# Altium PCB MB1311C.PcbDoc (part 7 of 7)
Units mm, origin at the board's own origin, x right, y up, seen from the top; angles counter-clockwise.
Board outline 100.03 x 67.03 mm, 6 copper layers (Top Layer, layer2, layer3, layer4, layer5, Bottom Layer), stack 1.208 mm thick; 366 components, 356 nets, 1582 pads, 964 vias.
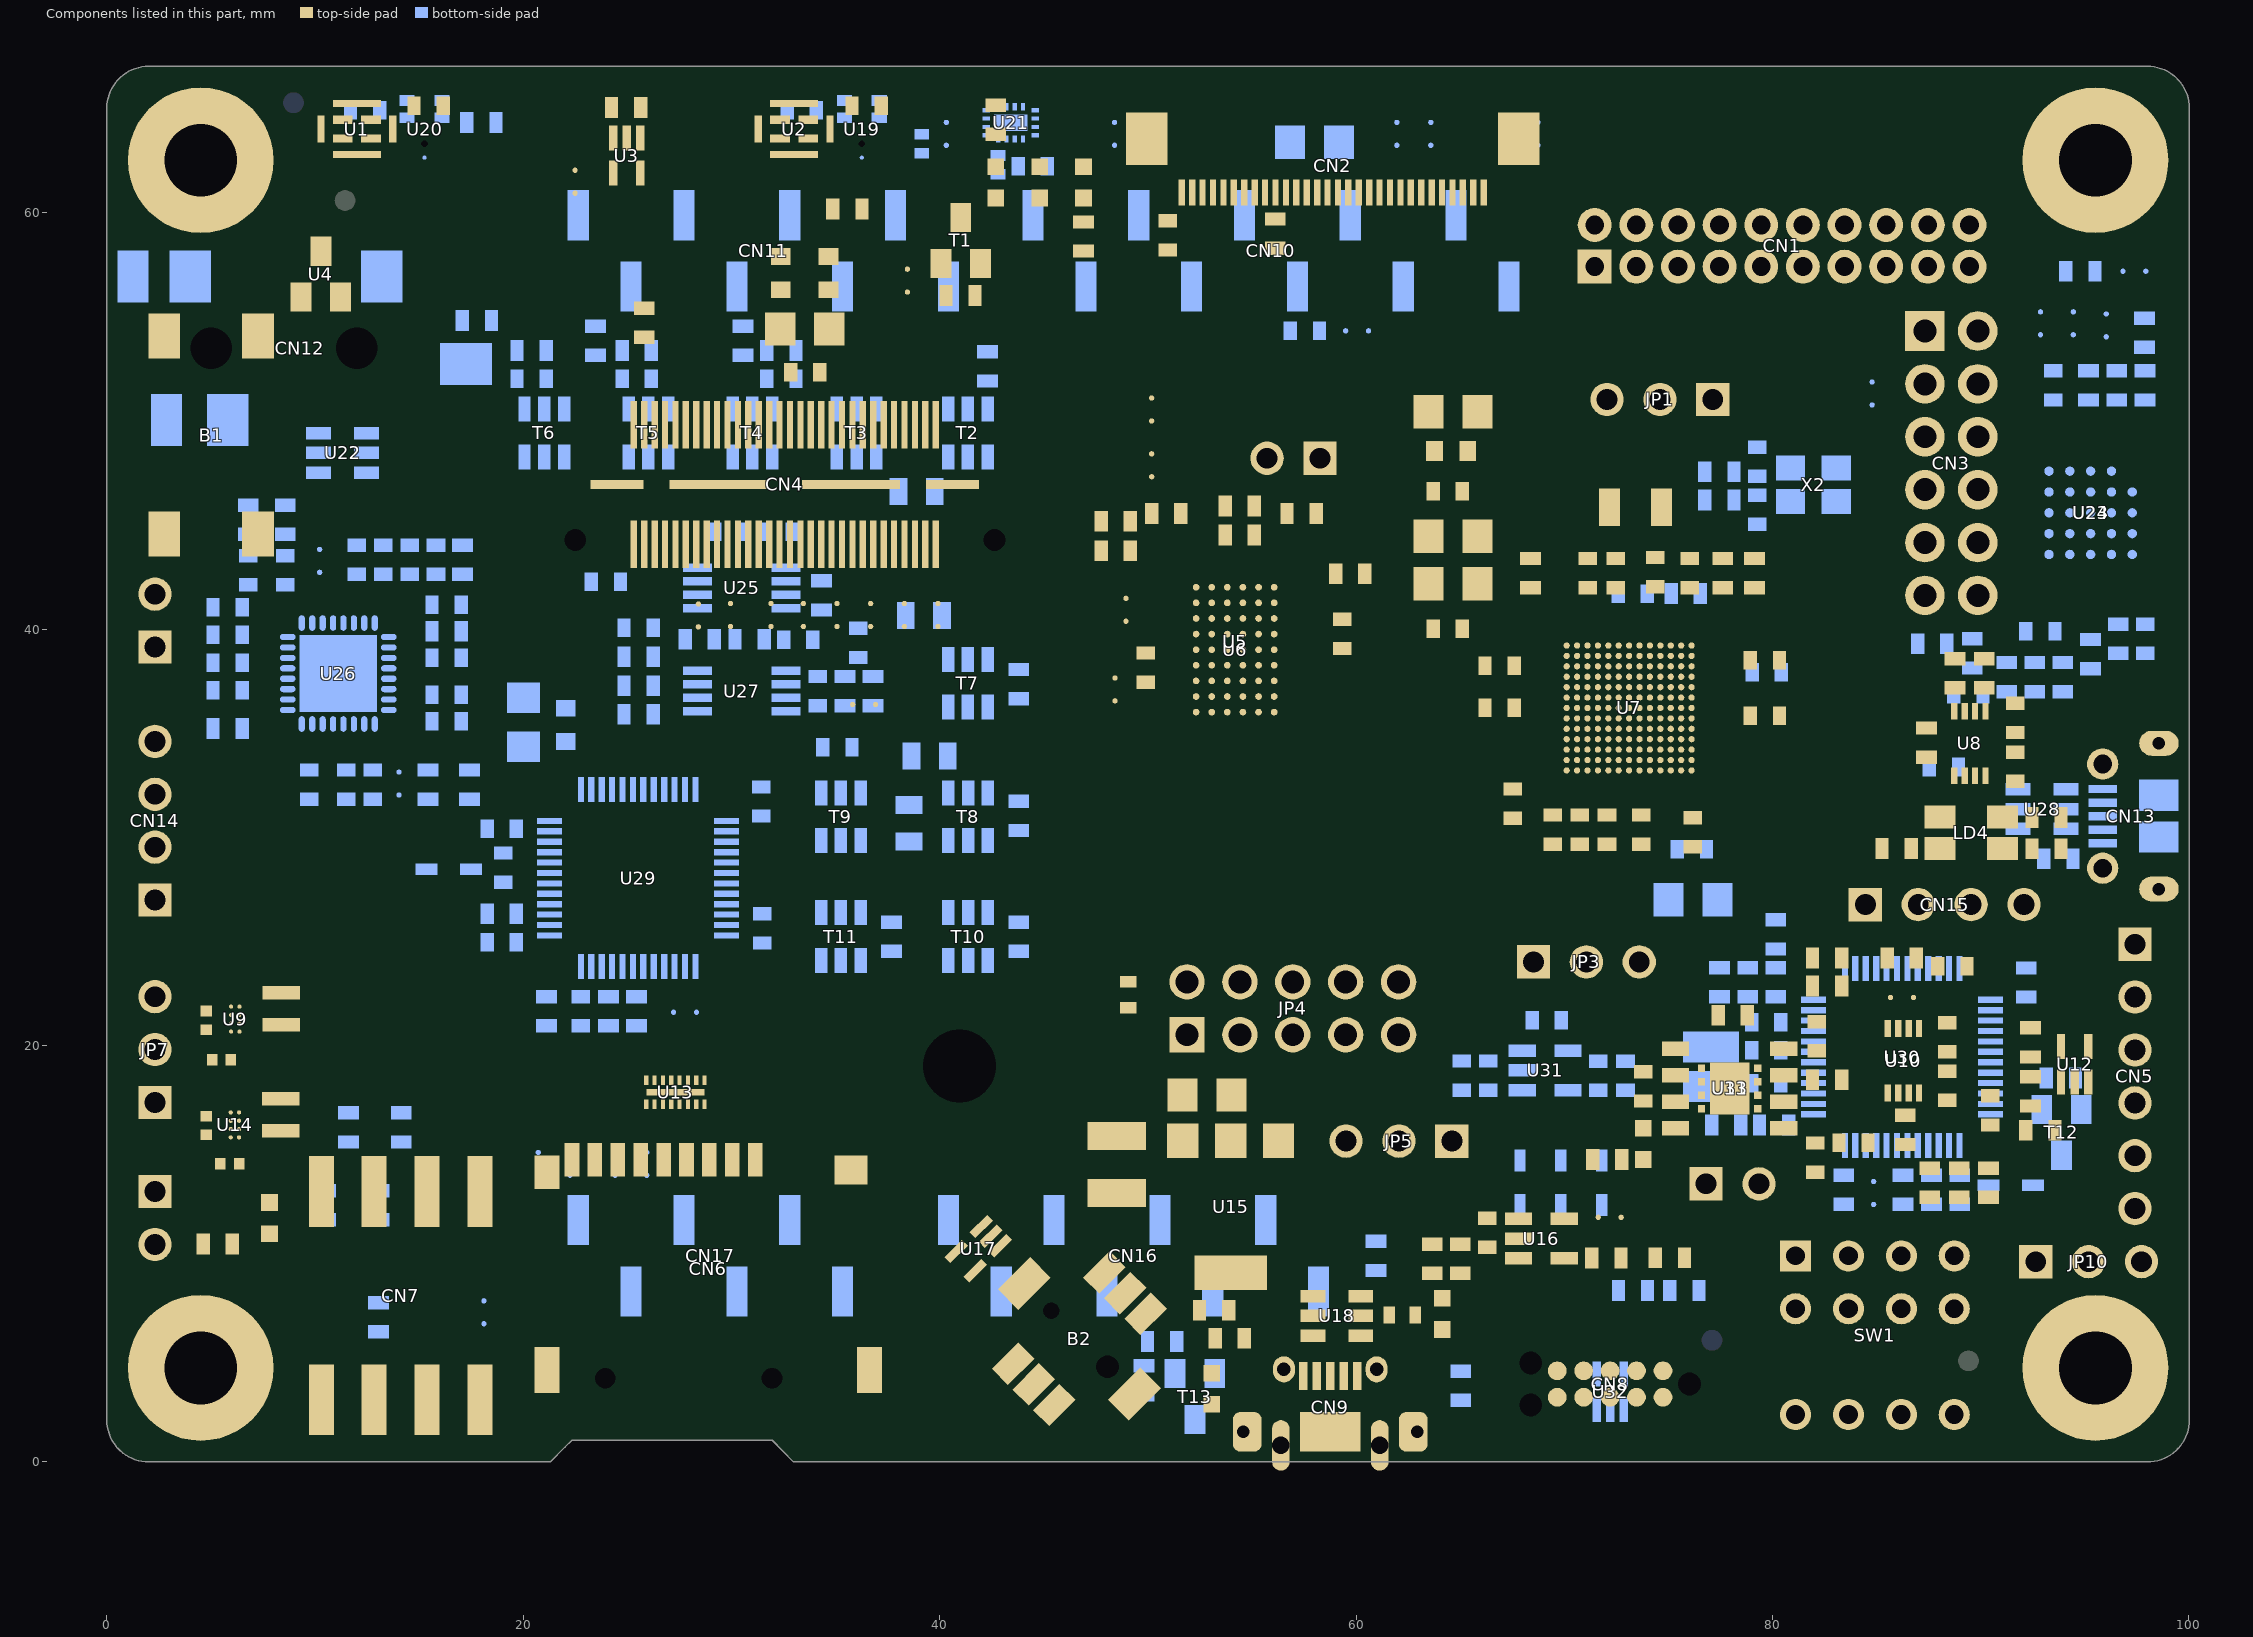
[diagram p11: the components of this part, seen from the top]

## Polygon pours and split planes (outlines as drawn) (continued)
+5V on layer4 "+5V_L04_P742" (solid, remove dead copper, pour order 742): 34.213,21.013 34.213,21.913 36.913,24.613 37.213,24.613 43.413,24.613 44.913,26.113 63.013,26.113 63.713,25.413 63.713,24.113 63.713,22.713 62.663,21.663 50.813,21.663 48.963,19.813 35.413,19.813
T50_4 on layer4 "T50_4_L04_P736" (solid, remove dead copper, pour order 736): 68.863,54.413 68.863,55.513 68.063,56.313 38.713,56.313 38.313,55.913 38.313,47.613 38.813,47.113 39.413,47.113 39.813,47.513 39.913,47.613 39.913,49.413 44.513,54.013 44.913,54.413 46.413,54.413
+3V3 on layer4 "+3V3_L04_P732" (solid, remove dead copper, pour order 732): 36.441,56.309 36.013,55.881 36.013,51.563 32.213,47.763 32.213,47.613 32.213,46.963 36.163,43.013 37.413,43.013 46.813,43.013 48.813,45.013 49.913,46.113 49.913,47.413 49.913,47.713 49.413,48.213 44.013,48.213 41.313,45.513 40.063,45.513 38.113,47.463 38.113,55.963 37.767,56.309
+3V3_ST_LINK on layer4 "+3V3_ST_LINK_L04_P716" (solid, remove dead copper, pour order 716): 80.813,24.513 85.313,29.013 89.213,29.013 90.213,28.013 90.213,26.013 90.213,25.913 89.313,25.013 89.313,20.413 89.313,19.663 87.413,17.763 87.413,16.813 87.413,16.513 87.813,16.113 87.913,16.013 88.513,16.013 88.613,16.013 89.413,16.813 92.013,16.813 94.113,14.713 94.213,14.613 94.213,13.113 94.213,12.713 92.413,10.913 92.363,10.863 79.913,10.863 79.013,11.763 79.013,13.473 80.813,15.273
1V8_CODEC on layer4 "1V8_CODEC_L04_P710" (solid, remove dead copper, pour order 710): 5.613,39.413 9.213,43.013 12.713,43.013 13.513,42.213 13.513,34.963 10.763,32.213 6.013,32.213 5.613,32.613
U5V_ST_LINK on layer4 "U5V_ST_LINK_L04_P746" (solid, remove dead copper, pour order 746): 51.963,21.063 65.963,21.063 71.013,16.013 71.013,15.113 70.363,14.463 68.913,14.463 67.613,14.463 65.313,16.763 64.363,17.713 54.113,17.713 52.363,17.713 51.213,18.863 51.213,20.313
VDD_STL on layer4 "VDD_STL_L04_P714" (solid, remove dead copper, pour order 714): 87.263,29.413 87.263,33.863 89.213,35.813 95.613,35.813 96.613,34.813 96.613,11.113 96.613,9.813 96.013,9.213 94.613,9.213 94.513,9.213 94.113,9.613 93.913,9.813 93.913,11.963 94.513,12.563 94.513,14.813 92.213,17.113 89.413,17.113 89.013,16.713 88.613,16.313 88.213,16.313 88.113,16.313 87.913,16.513 87.713,16.713 87.713,17.613 87.713,17.713 89.213,19.213 89.563,19.563 89.563,24.763 90.613,25.813 90.613,26.513 90.613,28.113 89.913,28.813 89.313,29.413
+1V8 on layer4 "+1V8_L04_P722" (solid, remove dead copper, pour order 722): 1.113,21.713 0.613,22.213 0.613,49.213 2.163,50.763 21.113,50.763 22.263,49.613 22.263,48.863 21.263,47.863 17.313,47.863 12.763,43.313 9.113,43.313 5.413,39.613 5.413,31.713 4.813,31.113 4.813,22.013 4.513,21.713
GND on layer5 "GND_L05_P705" (solid, remove dead copper, pour order 705): 0.013,67.013 0.1,66.926 100.068,66.926 100.068,0.068 100.013,0.013 0.013,0.013
AGND on layer5 "AGND_L05_P581" (solid, remove dead copper, pour order 581): 7.977,32.913 17.813,32.913 18.913,34.013 18.913,43.513 18.913,52.713 17.313,54.313 13.313,58.313 8.313,58.313 3.24,58.313 2.013,57.086 2.013,44.813 2.313,44.513 3.988,42.838 3.988,36.903
T50_6 on Bottom Layer "T50_6_L06_P706" (solid, remove dead copper, pour order 706): 36.213,47.413 37.313,46.313 37.313,45.513 38.613,45.513 38.613,41.527 37.793,41.527 37.793,39.777 39.65,39.777 39.65,34.768 38.073,34.768 38.073,33.018 39.208,33.018 39.213,32.413 37.613,32.413 36.913,33.113 36.913,34.913 36.913,35.313 37.713,36.113 37.713,38.013 36.718,39.008 36.718,41.708 35.613,42.813 33.468,42.813 32.713,42.813 32.713,43.113 33.113,43.113 33.513,43.513 33.913,43.913 33.913,46.213 33.913,46.313 34.813,47.213 34.813,47.413
NetCN5_1 on Bottom Layer "NETCN5_1_L06_P772" (solid, remove dead copper, pour order 772): 95.413,27.113 96.363,28.063 97.013,28.063 98.513,28.063 99.413,27.163 99.413,9.813 98.663,9.063 98.513,8.913 98.213,8.913 97.113,8.913 97.013,9.013 95.713,10.313 95.713,10.963 95.713,19.013 95.413,19.313
VIN on Bottom Layer "VIN_L06_P764" (solid, remove dead copper, pour order 764): 40.213,12.063 43.613,12.063 47.813,16.263 47.813,16.463 47.813,17.363 48.263,17.813 48.313,17.863 49.163,17.863 49.413,17.863 50.113,17.163 50.163,17.113 50.163,14.813 50.163,14.563 47.263,11.663 47.263,10.463 47.263,9.913 46.963,9.613 46.213,8.863 41.363,8.863 40.963,8.863 40.213,9.613
SH2_D on Bottom Layer "SH2_D_L06_P708" (solid, remove dead copper, pour order 708): 37.913,29.013 41.113,29.013 41.613,28.513 41.613,27.226 39.926,27.226 39.913,27.213 39.848,27.148 39.848,25.913 38.713,25.913 38.613,26.013 38.613,26.613 38.613,26.813 37.913,27.513
ARD_5V on Bottom Layer "ARD_5V_L06_P762" (solid, remove dead copper, pour order 762): 62.863,15.213 62.863,16.063 62.313,16.613 61.513,17.413 59.463,17.413 53.513,17.413 49.463,13.363 47.763,11.663 47.763,7.463 49.013,7.463 49.063,7.513 49.463,7.513 52.063,10.113 55.113,13.163 55.163,13.163 57.763,13.163 58.063,13.463 58.363,13.763 61.863,13.763 62.263,13.763 62.863,14.363
+3V3_ST_LINK on Bottom Layer "+3V3_ST_LINK_L06_P770" (solid, remove dead copper, pour order 770): 71.213,18.113 73.313,18.113 73.513,17.913 73.563,17.863 73.563,17.063 73.563,15.813 76.463,12.913 76.613,12.763 79.763,12.763 79.863,12.763 80.213,12.413 80.213,11.813 80.113,11.713 79.963,11.563 76.263,11.563 75.363,11.563 74.763,12.163 72.363,14.563 72.363,15.213 71.213,16.363
5V_USB_CHARGER on Bottom Layer "5V_USB_CHARGER_L06_P768" (solid, remove dead copper, pour order 768): 81.813,14.063 81.813,11.413 80.563,10.163 80.187,9.787 73.457,9.787 71.739,9.787 71.063,10.463 70.963,10.563 70.963,11.863 70.963,12.463 70.463,12.963 70.463,13.413 70.713,13.663 72.263,13.663 74.563,11.363 77.713,11.363 80.013,11.363 80.413,11.763 80.413,13.763 80.413,14.063 80.563,14.213 80.663,14.313 81.563,14.313
5V_STL on Bottom Layer "5V_STL_L06_P774" (solid, remove dead copper, pour order 774): 85.613,10.163 87.263,11.813 87.513,11.813 89.498,11.813 90.213,12.528 90.213,13.613 88.663,13.613 88.613,13.663 88.613,13.913 89.463,14.763 91.833,14.763 92.963,13.633 92.963,12.588 91.238,10.863 88.213,10.863 86.763,9.413 85.813,9.413 85.613,9.613 85.613,9.713
+3V3 on Top Layer "+3V3_L01_P740" (solid, remove dead copper, pour order 740): 79.113,66.413 40.463,66.413 37.313,63.263 37.313,60.413 35.913,59.013 35.913,56.113 35.913,55.713 36.213,55.413 37.613,55.413 37.613,57.913 37.913,58.213 38.613,58.913 40.313,58.913 40.313,61.113 40.813,61.613 41.563,62.363 41.563,63.613 79.113,63.613
+5V on Top Layer "+5V_L01_P748" (solid, remove dead copper, pour order 748): 10.661,20.784 12.64,22.763 35.298,22.763 35.571,22.49 35.571,22.103 35.034,21.566 34.84,21.372 34.419,21.372 33.975,20.928 32.111,19.064 6.947,19.064 6.821,19.19 6.821,19.47 7.001,19.651 8.133,19.651 9.202,19.651 10.339,20.789
5V_USB_CHARGER on Top Layer "5V_USB_CHARGER_L01_P744" (solid, remove dead copper, pour order 744): 61.013,21.913 62.613,21.913 63.313,21.213 63.413,21.113 63.413,18.013 63.413,14.413 63.113,14.113 61.913,14.113 60.553,12.753 59.543,12.753 59.323,12.973 59.323,13.723 60.613,15.013 60.613,21.513
+3V3 on Top Layer "+3V3_L01_P704" (solid, remove dead copper, pour order 704): 10.013,18.113 9.413,18.713 2.213,18.713 1.713,18.213 1.713,17.213 2.613,16.313 4.373,16.313 4.373,16.593 4.373,16.953 4.733,16.953 5.303,17.523 7.103,17.523 7.503,17.123 10.013,17.123
+1V8 on Top Layer "+1V8_L01_P702" (solid, remove dead copper, pour order 702): 9.913,23.213 9.313,23.813 1.813,23.813 1.513,23.513 1.513,22.313 2.413,21.413 4.383,21.413 4.383,21.683 4.383,22.003 4.703,22.003 5.313,22.613 7.113,22.613 7.513,22.213 9.913,22.213
+5V on Top Layer "+5V_L01_P754" (solid, remove dead copper, pour order 754): 63.813,15.263 63.863,15.313 63.863,21.213 63.863,21.563 63.113,22.313 63.113,23.863 65.363,23.863 65.663,23.563 66.313,22.913 66.313,17.863 66.313,15.763 65.813,15.263
VDD1 on Top Layer "VDD1_L01_P756" (solid, remove dead copper, pour order 756): 16.573,28.363 21.002,23.934 21.002,23.594 20.671,23.263 18.113,23.263 11.313,23.263 10.963,23.613 9.113,25.463 9.113,25.513 1.813,25.513 1.563,25.763 1.513,25.813 1.513,27.863 1.513,27.913 1.963,28.363
+5V on Top Layer "+5V_L01_P750" (solid, remove dead copper, pour order 750): 72.813,12.463 73.713,12.463 73.763,12.413 73.763,11.163 75.913,11.163 76.363,10.713 76.363,8.763 76.363,7.813 78.813,5.363 80.213,3.963 82.863,3.963 84.113,3.963 84.963,3.113 84.963,2.063 84.963,1.663 85.313,1.313 87.113,1.313 87.163,1.313 87.463,1.613 87.413,1.663 87.413,4.013 85.363,6.063 82.363,6.063 80.913,6.063 80.413,6.563 77.963,9.013 77.963,11.563 77.413,12.113 77.313,12.213 75.063,12.213 74.813,12.463 74.063,13.213 73.263,13.213 72.913,13.213 72.813,13.113
GND on Top Layer "GND_L01_P780" (solid, remove dead copper, pour order 780): 81.125,19.525 78.725,19.525 78.525,19.325 78.525,16.525 79.625,15.425 80.425,14.625 80.425,12.95 79.8,12.325 78.75,12.325 78.075,13 78.075,14.275 77.675,14.675 77,14.675 76.675,15 76.675,15.575 77.275,16.175 77.275,19.55 77.825,20.1 81.125,20.1
+5V on layer3 "+5V_L03_P738" (solid, remove dead copper, pour order 738): 4.113,22.413 5.013,23.313 5.813,23.313 7.513,23.313 8.013,22.813 8.813,22.013 8.813,16.313 8.813,13.913 6.813,11.913 6.513,11.613 2.713,11.613 1.213,11.613 0.913,11.913 0.913,13.813 0.913,14.613 1.213,14.913 1.613,15.313 3.013,15.313 3.313,15.313 4.113,16.113
5V_USB_CHARGER on layer3 "5V_USB_CHARGER_L03_P718" (solid, remove dead copper, pour order 718): 83.413,12.813 84.413,13.813 84.413,20.338 95.713,31.638 95.713,33.113 95.113,33.713 93.813,33.713 89.213,33.713 89.113,33.713 84.413,29.013 82.813,27.413 82.813,23.513 80.763,21.463 80.763,12.813
5V_USB_CHARGER on layer3 "5V_USB_CHARGER_L03_P766" (solid, remove dead copper, pour order 766): 59.513,13.663 70.963,13.663 72.013,12.613 72.913,11.713 72.913,10.863 72.913,10.713 72.613,10.413 71.713,10.413 70.613,10.413 69.663,11.363 69.563,11.463 61.013,11.463 60.163,11.463 59.313,12.313 59.213,12.413 59.213,13.363
AMP_5V on layer3 "AMP_5V_L03_P776" (solid, remove dead copper, pour order 776): 34.213,38.663 34.913,37.963 34.913,36.513 34.913,31.563 35.163,31.313 35.763,30.713 35.763,28.413 35.763,27.513 35.313,27.063 34.413,27.063 33.613,27.863 33.513,27.963 33.513,31.513 33.513,31.663 33.013,32.163 33.013,37.113 33.663,37.763 33.713,37.813 33.713,38.663
CAL_D on layer3 "CAL_D_L03_P778" (solid, remove dead copper, pour order 778): 40.963,35.163 40.963,33.413 42.913,31.463 42.913,26.563 42.913,26.513 43.413,26.013 43.463,25.963 43.463,23.863 43.463,23.513 43.263,23.313 42.463,23.313 41.013,24.763 41.013,27.463 41.013,30.563 40.013,31.563 40.013,34.963 40.013,35.363 40.213,35.563 40.663,35.563 40.963,35.263
VDD on layer3 "VDD_L03_P760" (solid, remove dead copper, pour order 760): 73.513,6.363 87.713,6.363 90.113,3.963 90.113,2.063 89.813,1.763 87.963,1.763 87.713,1.763 87.613,1.863 87.413,2.063 87.413,2.713 86.263,3.863 75.263,3.863 73.513,5.613
VDD1 on layer3 "VDD1_L03_P758" (solid, remove dead copper, pour order 758): 40.513,46.563 41.063,46.563 43.963,43.663 43.963,36.063 42.263,34.363 41.463,34.363 41.263,34.563 41.213,34.613 41.213,36.363 41.213,38.263 42.463,39.513 42.463,40.613 42.463,40.863 41.513,41.813 40.113,43.213 40.113,46.163
+5V on layer3 "+5V_L03_P752" (solid, remove dead copper, pour order 752): 64.463,16.213 71.963,16.213 72.913,15.263 74.513,13.663 74.513,12.013 74.513,11.763 74.163,11.413 73.613,11.413 73.563,11.413 73.263,11.713 72.713,12.263 71.013,13.963 64.313,13.963 63.763,14.513 63.763,14.563 63.763,16.213
GND on layer2 "GND_L02_P684" (solid, remove dead copper, pour order 684): 0.013,67.013 100.013,67.013 100.013,0.013 0.013,0.013

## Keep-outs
Top Layer:
  circle w0.025: c11.446,60.584 r1.2
  circle w0.025: c89.418,4.852 r1.2
  circle w0.01: c40.963,19.013 r3.5
Bottom Layer:
  circle w0.025: c8.971,65.279 r1.2
  circle w0.025: c77.095,5.839 r1.2
  circle w0.01: c40.963,19.013 r3.5
Keep-Out Layer:
  lines w0.1: 33.263,0 95.676,0 98.013,0 ccw(c98.013,2.013) 100.026,2.013 100.026,65.013 ccw(c98.013,65.013) 98.013,67.026 96.65,67.026 2.013,67.026 ccw(c2.013,65.013) 0,65.013 0,39.178 0,2.013 ccw(c2.013,2.013) 2.013,0 21.3,0 22.013,0.713 22.338,1.038 31.963,1.038 32.988,0 33.288,0
  text "BOARD OUTLINE" at 29.825,-22.8 h1.9
Multi-Layer:
  circle w0.01: c40.963,19.013 r2.2

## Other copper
Top Layer:
  pour cut-out: 25.013,18.988 25.013,20.938 25.538,21.463 31.588,21.463 32.288,20.763 32.288,19.738 31.538,18.988
  text "1" at 38.589,0.633 h0.8
  text "1" at 43.1,-17.675 h2
  text "PRIMARY SIDE" at 28.81,-22.755 h2
layer2:
  text "2" at 39.229,0.633 h0.8
  text "2" at 43.1,-17.675 h2
  text "LAYER 2 (GND PLANE)" at 28.81,-22.755 h2
layer3:
  text "3" at 40.154,0.633 h0.8
  text "3" at 43.1,-17.675 h2
  text "LAYER 3" at 28.81,-22.755 h2
layer4:
  pour cut-out: 31.013,21.488 31.363,21.138 31.363,20.738 31.038,20.413 30.488,20.413 30.263,20.638 30.263,21.163 30.588,21.488
  text "4" at 41.055,0.633 h0.8
  text "4" at 43.1,-17.675 h2
  text "LAYER 4 (VCC PLANE)" at 28.81,-22.755 h2
layer5:
  text "5" at 41.913,0.633 h0.8
  text "5" at 43.1,-17.675 h2
  text "LAYER 5 (GND PLANE)" at 28.81,-22.755 h2
Bottom Layer:
  text "6" at 43.383,0.633 h0.8
  text "6" at 43.1,-17.675 h2
  text "SECONDARY SIDE" at 28.81,-22.755 h2
Multi-Layer:
  circle w0.2: c-9.925,73.113 r1.922
  circle w0.2: c-9.925,73.113 r3.442
  circle w0.2: c107.825,82.863 r1.922
  circle w0.2: c107.825,82.863 r3.442
  circle w0.2: c-8.925,-5.887 r1.922
  circle w0.2: c-8.925,-5.887 r3.442
  pour cut-out: 38.263,2.013 38.263,0.013 43.763,0.013 43.763,2.013
  lines w0.2: -15.894,73.05 -3.892,73.05 ; -14.894,-5.95 -2.892,-5.95 ; -9.925,67.017 -9.925,79.019 ; -8.925,-11.983 -8.925,0.019 ; 101.856,82.8 113.858,82.8 ; 107.825,76.767 107.825,88.769

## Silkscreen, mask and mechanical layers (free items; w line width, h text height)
Top Overlay:
  drawing of 1896 lines, arcs and shapes, not listed
  text "www.st.com/stm32l4-discovery" at 11.388,58.713 h0.9
  text "CAMERA" at 62.32,57.684 h1
  text "STM32L4R9I-DISCO" at 13.313,56.888 h1.1
  text "MB1311C" at 12.938,54.913 h1.2
  text "STMod+" at 74.413,54.263 h1
  text "IDD" at 76.313,48.238 h1
  text "VDD" at 70.613,48.213 h1
  text "PMOD" at 81.513,47.463 h1
  text "RESET" at 1.638,47.363 h1 r90
  text "DSI LCD" at 14.988,46.363 h1
  text "USB" at 96.488,36.937 h0.9
  text "STLINK" at 96.038,35.787 h0.8
  text "COM" at 84.124,30.697 h0.9
  text "SWD" at 4.063,30.563 h0.9
  text "(3)E5V" at 54.913,24.763 h1 r90
  text "(5)U5V" at 57.363,24.763 h1 r90
  text "(9)CHGR" at 62.463,24.763 h1 r90
  text "(1)STLK" at 52.363,24.738 h1 r90
  text "(7)ARD" at 59.938,24.738 h1 r90
  text "VDD" at 99.775,23.975 h0.8 r90
  text "10" at 63.913,23.163 h1
  text "SWD" at 92.913,22.613 h0.9
  text "VDD-MCU" at 71.1,21.65 h0.8
  text "CLK" at 99.788,21.538 h0.8 r90
  text "+3V3" at 66.338,21.388 h0.9
  text "9" at 63.988,19.163 h1
  text "GND" at 99.788,19.088 h0.8 r90
  text "ARD-5V" at 62.463,17.163 h1
  text "SWIO" at 99.763,16.313 h0.8 r90
  text "OUT" at 66.363,15.663 h1
  text "EXT-I2C" at 11.688,15.388 h0.9
  text "NRST" at 99.788,13.238 h0.8 r90
  text "IN" at 58.663,12.713 h1
  text "SWO" at 99.813,10.588 h0.8 r90
  text "uSD" at 36.875,6.35 h0.9
  text "JOYSTICK" at 37.863,2.588 h0.8
  text "OTG-FS" at 64.913,0.613 h0.8 r90
  text "TAG" at 77.463,0.513 h1
  text "SILKSCREEN, (PRIMARY)" at 28.81,-22.755 h2
Bottom Overlay:
  drawing of 252 lines, arcs and shapes, not listed
  text "PI7" at 72.316,64.167 h0.8 r270
  text "PA4" at 74.745,64.034 h0.8 r270
  text "PA5" at 77.068,64.034 h0.8 r270
  text "+5V" at 79.11,64.034 h0.8 r270
  text "GND" at 81.11,64.034 h0.8 r270
  text "PC2" at 85.11,64.033 h0.8 r270
  text "PC7" at 87.11,64.033 h0.8 r270
  text "PC2" at 89.11,64.033 h0.8 r270
  text "PC6" at 70.304,64.024 h0.8 r270
  text "PB12" at 83.097,63.588 h0.8 r270
  text "15" at 71.628,62.303 h0.8 r270
  text "14" at 74.113,62.013 h0.8 r270
  text "CN1 Table" at 90.813,60.913 h0.8 r270
  text "GND" at 79.135,60.878 h0.8 r270
  text "PG7" at 83.119,60.878 h0.8 r270
  text "PI3" at 85.11,60.878 h0.8 r270
  text "PI2" at 87.11,60.878 h0.8 r270
  text "PG8" at 89.094,60.878 h0.8 r270
  text "PA6" at 70.256,60.798 h0.8 r270
  text "PB11" at 75.058,60.771 h0.8 r270
  text "+5V" at 81.11,60.745 h0.8 r270
  text "PB10" at 72.709,60.713 h0.8 r270
  text "PA15" at 76.414,60.702 h0.8 r270
  text "PB13" at 77.466,60.702 h0.8 r270
  text "D1" at 24.713,59.763 h0.8 r270
  text "D3" at 29.938,59.713 h0.8 r270
  text "D5" at 35.025,59.7 h0.8 r270
  text "D13" at 56.853,59.707 h0.8 r270
  text "D11" at 51.85,59.675 h0.8 r270
  text "AUDIO jack" at 17.463,59.088 h1
  text "11" at 70.513,58.913 h1
  text "20" at 92.113,58.913 h1
  text "1" at 70.413,56.913 h1
  text "10" at 92.013,56.913 h1
  text "GND" at 60.704,55.814 h0.8
  text "D0" at 22.225,55.5 h0.8 r270
  text "D6" at 37.517,55.514 h0.8 r270
  text "1" at 86.813,55.513 h1 r270
  text "D2" at 27.388,55.438 h0.8 r270
  text "D4" at 32.438,55.438 h0.8 r270
  text "7" at 89.313,55.413 h1 r270
  text "D8" at 43.963,55.388 h0.8 r270
  text "D10" at 49.165,54.801 h0.8 r270
  text "D12" at 54.402,54.801 h0.8 r270
  text "D14" at 64.568,54.763 h0.8 r270
  text "D9" at 46.613,53.788 h0.8 r270
  text "D7" at 40.01,53.688 h0.8 r270
  text "D15" at 66.951,53.163 h0.8 r270
  text "AVDD" at 61.887,52.242 h0.8 r270
  text "6" at 85.113,41.313 h1 r270
  text "12" at 91.013,40.988 h1 r270
  text "GND" at 89.225,28.325 h0.8 r315
  text "SWCLK" at 86.95,28.3 h0.8 r315
  text "SWIO" at 91.375,28.275 h0.8 r315
  text "+3V3" at 84.525,28.225 h0.8 r315
  text "+1V8" at 7.594,21.867 h1
  text "ARD" at 59.113,16.988 h0.8 r270
  text "E5V" at 53.988,16.963 h0.8 r270
  text "U5V" at 56.538,16.913 h0.8 r270
  text "+3V3" at 7.798,16.718 h1
  text "STLK" at 51.438,16.563 h0.8 r270
  text "CHGR" at 62.399,16.438 h0.8 r270
  text "VIN" at 40.063,13.163 h0.8 r270
  text "GND" at 45.163,13.163 h0.8 r270
  text "3V3" at 50.163,13.113 h0.8 r270
  text "IOREF" at 55.263,13.113 h0.8 r270
  text "5V" at 47.663,11.413 h0.8 r270
  text "NRST" at 52.763,11.413 h0.8 r270
  text "GND" at 42.613,11.363 h0.8 r270
  text "1" at 78.813,9.213 h1.1
  text "A1" at 32.463,5.563 h0.8 r270
  text "A2" at 29.863,5.338 h0.8 r270
  text "A0" at 34.938,5.313 h0.8 r270
  text "A3" at 27.263,5.288 h0.8 r270
  text "A5" at 22.313,5.263 h0.8 r270
  text "A4" at 24.813,5.263 h0.8 r270
  text "SILKSCREEN, (SECONDARY)" at 69.57,-22.755 h2
Top Paste:
  text "SOLDER PASTE, (PRIMARY)" at 29.625,-21.325 h2
  text "ALL" at 29.575,-24.925 h2
Bottom Paste:
  text "SOLDER PASTE, (SECONDARY)" at 28.26,-22.755 h2
Top Solder:
  region: 38.263,2.013 38.263,0.263 43.763,0.263 43.763,2.013
  text "SOLDER MASK, (PRIMARY)" at 28.81,-22.755 h2
Bottom Solder:
  region: 38.263,2.013 38.263,0.263 43.763,0.263 43.763,2.013
  text "SOLDER MASK, (SECONDARY)" at 28.81,-22.755 h2
Mechanical 2:
  circle w0.2: c-9.925,73.113 r1.922
  circle w0.2: c-9.925,73.113 r3.442
  circle w0.2: c107.825,82.863 r1.922
  circle w0.2: c107.825,82.863 r3.442
  circle w0.2: c-8.925,-5.887 r1.922
  circle w0.2: c-8.925,-5.887 r3.442
  lines w0.2: -15.894,73.05 -3.892,73.05 ; -14.894,-5.95 -2.892,-5.95 ; -9.925,67.017 -9.925,79.019 ; -8.925,-11.983 -8.925,0.019 ; 101.856,82.8 113.858,82.8 ; 107.825,76.767 107.825,88.769
Mechanical 3:
  text "+ U11" at 36.15,-25 h2
Mechanical 4:
  text "+ U33" at 46.375,-25.025 h2
Mechanical 11:
  drawing of 338 lines, arcs and shapes, not listed
  text "Vue Top (connecteur en bottom)" at 9.838,53.863 h1.5
  text "2" at 39.699,43.656 h0.41
  text "MB1314A" at 25.863,17.588 h1.5
  text "ASSEMBLY DRAWING, (MB1314A)" at 28.75,-23 h1.8
Drill Drawing:
  drawing of 574 lines, arcs and shapes, not listed
  text "Layer" at 21.1,103.85 h1
  text "Name" at 26.771,103.85 h1
  text "Material" at 39.383,103.85 h1
  text "Thickness" at 50.29,103.85 h1
  text "Constant" at 58.722,103.85 h1
  text "Board Layer Stack" at 66.802,103.85 h1
  text "1" at 21.1,101.85 h1
  text "Top Overlay" at 26.771,101.85 h1
  text "2" at 21.1,99.85 h1
  text "Top Solder" at 26.771,99.85 h1
  text "Solder Resist" at 39.383,99.85 h1
  text "0,39mil" at 50.29,99.85 h1
  text "3,5" at 58.722,99.85 h1
  text "3" at 21.1,97.85 h1
  text "Top Layer" at 26.771,97.85 h1
  text "Copper" at 39.383,97.85 h1
  text "1,65mil" at 50.29,97.85 h1
  text "4" at 21.1,95.85 h1
  text "Dielectric 1" at 26.771,95.85 h1
  text "FR-4" at 39.383,95.85 h1
  text "2,83mil" at 50.29,95.85 h1
  text "4,2" at 58.722,95.85 h1
  text "5" at 21.1,93.85 h1
  text "layer2" at 26.771,93.85 h1
  text "Copper" at 39.383,93.85 h1
  text "1,38mil" at 50.29,93.85 h1
  text "6" at 21.1,91.85 h1
  text "Dielectric 2" at 26.771,91.85 h1
  text "FR-4" at 39.383,91.85 h1
  text "3,09mil" at 50.29,91.85 h1
  text "4,3" at 58.722,91.85 h1
  text "7" at 21.1,89.85 h1
  text "layer3" at 26.771,89.85 h1
  text "Copper" at 39.383,89.85 h1
  text "0,69mil" at 50.29,89.85 h1
  text "8" at 21.1,87.85 h1
  text "Dielectric 3" at 26.771,87.85 h1
  text "FR-4" at 39.383,87.85 h1
  text "27,95mil" at 50.29,87.85 h1
  text "4,3" at 58.722,87.85 h1
  text "9" at 21.1,85.85 h1
  text "layer4" at 26.771,85.85 h1
  text "Copper" at 39.383,85.85 h1
  text "0,69mil" at 50.29,85.85 h1
  text "10" at 21.1,83.85 h1
  text "Dielectric 4" at 26.771,83.85 h1
  text "FR-4" at 39.383,83.85 h1
  text "3,42mil" at 50.29,83.85 h1
  text "4,3" at 58.722,83.85 h1
  text "11" at 21.1,81.85 h1
  text "layer5" at 26.771,81.85 h1
  text "Copper" at 39.383,81.85 h1
  text "1,38mil" at 50.29,81.85 h1
  text "12" at 21.1,79.85 h1
  text "Dielectric 5" at 26.771,79.85 h1
  text "FR-4" at 39.383,79.85 h1
  text "2,83mil" at 50.29,79.85 h1
  text "4,2" at 58.722,79.85 h1
  text "13" at 21.1,77.85 h1
  text "Bottom Layer" at 26.771,77.85 h1
  text "Copper" at 39.383,77.85 h1
  text "1,65mil" at 50.29,77.85 h1
  text "14" at 21.1,75.85 h1
  text "Bottom Solder" at 26.771,75.85 h1
  text "Solder Resist" at 39.383,75.85 h1
  text "0,39mil" at 50.29,75.85 h1
  text "3,5" at 58.722,75.85 h1
  text "15" at 21.1,73.85 h1
  text "Bottom Overlay" at 26.771,73.85 h1
  text "Symbol" at 105.775,71.425 h0.96
  text "Count" at 111.705,71.425 h0.96
  text "Hole Size" at 117.506,71.425 h0.96
  text "Plated" at 129.272,71.425 h0.96
  text "Hole Type" at 134.393,71.425 h0.96
  text "Drill Layer Pair" at 142.079,71.425 h0.96
  text "Via/Pad" at 154.027,71.425 h0.96
  text "79" at 111.705,69.425 h0.8
  text "0,100mm (3,94mil)" at 117.506,69.425 h0.8
  text "PTH" at 129.272,69.425 h0.8
  text "Round" at 134.393,69.425 h0.8
  text "Top Layer - layer3" at 142.079,69.425 h0.8
  text "Via" at 154.027,69.425 h0.8
  text "G" at 105.424,69.345 h0.89
  text "79 Total" at 111.705,67.425 h0.8
  text "Symbol" at 105.775,63.925 h0.96
  text "Count" at 111.705,63.925 h0.96
  text "Hole Size" at 117.506,63.925 h0.96
  text "Plated" at 129.272,63.925 h0.96
  text "Hole Type" at 134.393,63.925 h0.96
  text "Drill Layer Pair" at 142.079,63.925 h0.96
  text "Via/Pad" at 156.187,63.925 h0.96
  text "53" at 111.705,61.925 h0.8
  text "0,100mm (3,94mil)" at 117.506,61.925 h0.8
  text "PTH" at 129.272,61.925 h0.8
  text "Round" at 134.393,61.925 h0.8
  text "layer5 - Bottom Layer" at 142.079,61.925 h0.8
  text "Via" at 156.187,61.925 h0.8
  text "F" at 105.424,61.845 h0.89
  text "53 Total" at 111.705,59.925 h0.8
  text "Symbol" at 105.775,56.425 h0.96
  text "Count" at 111.705,56.425 h0.96
  text "Hole Size" at 117.925,56.425 h0.96
  text "Plated" at 130.403,56.425 h0.96
  text "Hole Type" at 135.524,56.425 h0.96
  text "Drill Layer Pair" at 143.21,56.425 h0.96
  text "Via/Pad" at 154.031,56.425 h0.96
  text "4" at 111.705,54.425 h0.8
  text "0,254mm (10,00mil)" at 117.925,54.425 h0.8
  text "PTH" at 130.403,54.425 h0.8
  text "Round" at 135.524,54.425 h0.8
  text "layer2 - layer5" at 143.21,54.425 h0.8
  text "Via" at 154.031,54.425 h0.8
  text "E" at 105.424,54.345 h0.89
  text "112" at 111.705,52.425 h0.8
  text "0,203mm (8,00mil)" at 117.925,52.425 h0.8
  text "PTH" at 130.403,52.425 h0.8
  text "Round" at 135.524,52.425 h0.8
  text "layer2 - layer5" at 143.21,52.425 h0.8
  text "Via" at 154.031,52.425 h0.8
  text "D" at 105.424,52.345 h0.89
  text "116 Total" at 111.705,50.425 h0.8
  text "Symbol" at 105.775,46.925 h0.96
  text "Count" at 111.705,46.925 h0.96
  text "Hole Size" at 117.506,46.925 h0.96
  text "Plated" at 129.272,46.925 h0.96
  text "Hole Type" at 134.393,46.925 h0.96
  text "Drill Layer Pair" at 142.079,46.925 h0.96
  text "Via/Pad" at 154.027,46.925 h0.96
  text "80" at 111.705,44.925 h0.8
  text "0,100mm (3,94mil)" at 117.506,44.925 h0.8
  text "PTH" at 129.272,44.925 h0.8
  text "Round" at 134.393,44.925 h0.8
  text "Top Layer - layer2" at 142.079,44.925 h0.8
  text "Via" at 154.027,44.925 h0.8
  text "C" at 105.424,44.845 h0.89
  text "80 Total" at 111.705,42.925 h0.8
  text "Symbol" at 105.775,39.431 h0.96
  text "Count" at 111.705,39.431 h0.96
  text "Hole Size" at 118.219,39.431 h0.96
  text "Plated" at 131.408,39.431 h0.96
  text "Hole Type" at 136.53,39.431 h0.96
  text "Drill Layer Pair" at 144.215,39.431 h0.96
  text "Via/Pad" at 160.544,39.431 h0.96
  text "Hole Length" at 166.922,39.431 h0.96
  text "Routed Path Length" at 179.525,39.431 h0.96
  text "1" at 111.705,37.431 h0.8
  text "0,800mm (31,50mil)" at 118.219,37.431 h0.8
  text "NPTH" at 131.408,37.431 h0.8
  text "Round" at 136.53,37.431 h0.8
  text "Top Layer - Bottom Layer" at 144.215,37.431 h0.8
  text "Pad" at 160.544,37.431 h0.8
  text "-" at 166.922,37.431 h0.8
  text "-" at 179.525,37.431 h0.8
  text "1" at 111.705,35.431 h0.8
  text "3,500mm (137,80mil)" at 118.219,35.431 h0.8
  text "NPTH" at 131.408,35.431 h0.8
  text "Round" at 136.53,35.431 h0.8
  text "Top Layer - Bottom Layer" at 144.215,35.431 h0.8
  text "Pad" at 160.544,35.431 h0.8
  text "-" at 166.922,35.431 h0.8
  text "-" at 179.525,35.431 h0.8
  text "2" at 111.705,33.431 h0.8
  text "0,325mm (12,80mil)" at 118.219,33.431 h0.8
  text "NPTH" at 131.408,33.431 h0.8
  text "Round" at 136.53,33.431 h0.8
  text "Top Layer - Bottom Layer" at 144.215,33.431 h0.8
  text "Pad" at 160.544,33.431 h0.8
  text "-" at 166.922,33.431 h0.8
  text "-" at 179.525,33.431 h0.8
  text "2" at 111.705,31.431 h0.8
  text "0,650mm (25,59mil)" at 118.219,31.431 h0.8
  text "PTH" at 131.408,31.431 h0.8
  text "Slot" at 136.53,31.431 h0.8
  text "Top Layer - Bottom Layer" at 144.215,31.431 h0.8
  text "Pad" at 160.544,31.431 h0.8
  text "0,850mm (33,47mil)" at 166.922,31.431 h0.8
  text "0,200mm (7,88mil)" at 179.525,31.431 h0.8
  text "2" at 111.705,29.431 h0.8
  text "0,850mm (33,47mil)" at 118.219,29.431 h0.8
  text "NPTH" at 131.408,29.431 h0.8
  text "Slot" at 136.53,29.431 h0.8
  text "Top Layer - Bottom Layer" at 144.215,29.431 h0.8
  text "Pad" at 160.544,29.431 h0.8
  text "2,425mm (95,47mil)" at 166.922,29.431 h0.8
  text "1,575mm (62,01mil)" at 179.525,29.431 h0.8
  text "2" at 111.705,27.431 h0.8
  text "1,000mm (39,37mil)" at 118.219,27.431 h0.8
  text "NPTH" at 131.408,27.431 h0.8
  text "Round" at 136.53,27.431 h0.8
  text "Top Layer - Bottom Layer" at 144.215,27.431 h0.8
  text "Pad" at 160.544,27.431 h0.8
  text "-" at 166.922,27.431 h0.8
  text "-" at 179.525,27.431 h0.8
  text "H" at 105.424,27.352 h0.89
  text "2" at 111.705,25.431 h0.8
  text "1,050mm (41,34mil)" at 118.219,25.431 h0.8
  text "NPTH" at 131.408,25.431 h0.8
  text "Round" at 136.53,25.431 h0.8
  text "Top Layer - Bottom Layer" at 144.215,25.431 h0.8
  text "Pad" at 160.544,25.431 h0.8
  text "-" at 166.922,25.431 h0.8
  text "-" at 179.525,25.431 h0.8
  text "2" at 111.705,23.431 h0.8
  text "2,000mm (78,74mil)" at 118.219,23.431 h0.8
  text "NPTH" at 131.408,23.431 h0.8
  text "Round" at 136.53,23.431 h0.8
  text "Top Layer - Bottom Layer" at 144.215,23.431 h0.8
  text "Pad" at 160.544,23.431 h0.8
  text "-" at 166.922,23.431 h0.8
  text "-" at 179.525,23.431 h0.8
  text "4" at 111.705,21.431 h0.8
  text "0,600mm (23,62mil)" at 118.219,21.431 h0.8
  text "PTH" at 131.408,21.431 h0.8
  text "Slot" at 136.53,21.431 h0.8
  text "Top Layer - Bottom Layer" at 144.215,21.431 h0.8
  text "Pad" at 160.544,21.431 h0.8
  text "1,300mm (51,18mil)" at 166.922,21.431 h0.8
  text "0,700mm (27,56mil)" at 179.525,21.431 h0.8
  text "4" at 111.705,19.431 h0.8
  text "1,100mm (43,31mil)" at 118.219,19.431 h0.8
  text "NPTH" at 131.408,19.431 h0.8
  text "Round" at 136.53,19.431 h0.8
  text "Top Layer - Bottom Layer" at 144.215,19.431 h0.8
  text "Pad" at 160.544,19.431 h0.8
  text "-" at 166.922,19.431 h0.8
  text "-" at 179.525,19.431 h0.8
  text "4" at 111.705,17.431 h0.8
  text "3,500mm (137,80mil)" at 118.219,17.431 h0.8
  text "PTH" at 131.408,17.431 h0.8
  text "Round" at 136.53,17.431 h0.8
  text "Top Layer - Bottom Layer" at 144.215,17.431 h0.8
  text "Pad" at 160.544,17.431 h0.8
  text "-" at 166.922,17.431 h0.8
  text "-" at 179.525,17.431 h0.8
  text "22" at 111.705,15.431 h0.8
  text "1,100mm (43,31mil)" at 118.219,15.431 h0.8
  text "PTH" at 131.408,15.431 h0.8
  text "Round" at 136.53,15.431 h0.8
  text "Top Layer - Bottom Layer" at 144.215,15.431 h0.8
  text "Pad" at 160.544,15.431 h0.8
  text "-" at 166.922,15.431 h0.8
  text "-" at 179.525,15.431 h0.8
  text "34" at 111.705,13.431 h0.8
  text "0,900mm (35,43mil)" at 118.219,13.431 h0.8
  text "PTH" at 131.408,13.431 h0.8
  text "Round" at 136.53,13.431 h0.8
  text "Top Layer - Bottom Layer" at 144.215,13.431 h0.8
  text "Pad" at 160.544,13.431 h0.8
  text "-" at 166.922,13.431 h0.8
  text "-" at 179.525,13.431 h0.8
  text "37" at 111.705,11.431 h0.8
  text "1,000mm (39,37mil)" at 118.219,11.431 h0.8
  text "PTH" at 131.408,11.431 h0.8
  text "Round" at 136.53,11.431 h0.8
  text "Top Layer - Bottom Layer" at 144.215,11.431 h0.8
  text "Pad" at 160.544,11.431 h0.8
  text "-" at 166.922,11.431 h0.8
  text "-" at 179.525,11.431 h0.8
  text "48" at 111.705,9.431 h0.8
  text "0,203mm (8,00mil)" at 118.219,9.431 h0.8
  text "PTH" at 131.408,9.431 h0.8
  text "Round" at 136.53,9.431 h0.8
  text "Top Layer - Bottom Layer" at 144.215,9.431 h0.8
  text "Via" at 160.544,9.431 h0.8
  text "-" at 166.922,9.431 h0.8
  text "-" at 179.525,9.431 h0.8
  text "B" at 105.424,9.352 h0.89
  text "126" at 111.705,7.431 h0.8
  text "0,305mm (12,00mil)" at 118.219,7.431 h0.8
  text "PTH" at 131.408,7.431 h0.8
  text "Round" at 136.53,7.431 h0.8
  text "Top Layer - Bottom Layer" at 144.215,7.431 h0.8
  text "Via" at 160.544,7.431 h0.8
  text "-" at 166.922,7.431 h0.8
  text "-" at 179.525,7.431 h0.8
  text "A" at 105.424,7.352 h0.89
  text "462" at 111.705,5.431 h0.8
  text "0,254mm (10,00mil)" at 118.219,5.431 h0.8
  text "PTH" at 131.408,5.431 h0.8
  text "Round" at 136.53,5.431 h0.8
  text "Top Layer - Bottom Layer" at 144.215,5.431 h0.8
  text "Via" at 160.544,5.431 h0.8
  text "-" at 166.922,5.431 h0.8
  text "-" at 179.525,5.431 h0.8
  text "755 Total" at 111.705,3.431 h0.8
  text "Slot definitions :" at 105.775,1.605 h0.8
  text "Routed Path Length" at 115.431,1.605 h0.8
  text "= Calculated from tool start centre position to tool end centre position." at 126.981,1.605 h0.8
  text "Hole Length" at 115.431,0.379 h0.8
  text "= Routed Path Length + Tool Size = Slot length as defined in the PCB layout" at 122.414,0.379 h0.8
  text "FAB DRAWING & DRILL LEGEND" at 28.813,-22.763 h1.9
Mechanical 27:
  lines w0.1: 33.263,0 95.676,0 98.013,0 ccw(c98.013,2.013) 100.026,2.013 100.026,65.013 ccw(c98.013,65.013) 98.013,67.026 96.65,67.026 2.013,67.026 ccw(c2.013,65.013) 0,65.013 0,39.178 0,2.013 ccw(c2.013,2.013) 2.013,0 21.3,0 ; 33.288,0 32.988,0 31.963,1.038 22.338,1.038 21.3,0 ; 21.3,0 21.3,0
  text "ASSEMBLY DRAWING, (PRIMARY)" at 28.26,-22.755 h1.9
Mechanical 30:
  lines w0.1: 33.263,0 95.676,0 98.013,0 ccw(c98.013,2.013) 100.026,2.013 100.026,65.013 ccw(c98.013,65.013) 98.013,67.026 96.65,67.026 2.013,67.026 ccw(c2.013,65.013) 0,65.013 0,39.178 0,2.013 ccw(c2.013,2.013) 2.013,0 21.3,0 ; 33.288,0 32.988,0 31.963,1.038 22.338,1.038 21.3,0 ; 21.3,0 21.3,0
  text "ASSEMBLY DRAWING, (SECONDARY)" at 72.486,-22.755 h1.7

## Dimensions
0,65.013 to 100.026,65.013 on Drill Drawing
2.013,67.026 to 2.013,0 on Drill Drawing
